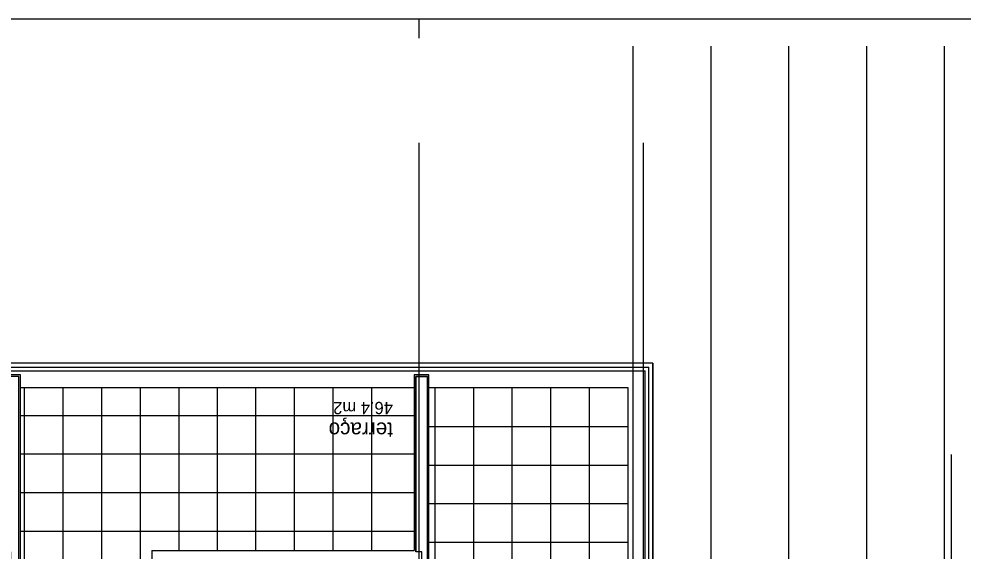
# Model space of a CAD drawing. Extents: x 1278 to 1356, y -253.7 to -224.
# Drawn here: x 1291.33 to 1303.56, y -230.86 to -223.96 of the extents above; entities that cross this region are included whole.
import ezdxf

# ---------------------------------------------------------------- set-up
doc = ezdxf.new("R2010")
doc.units = 0
for name, color, linetype in [('Level 1', 7, 'Continuous'), ('Level 2', 7, 'Continuous'), ('Level 21', 7, 'Continuous'), ('Level 60', 7, 'Continuous'), ('Level 62', 7, 'Continuous'), ('Level 65', 7, 'Continuous'), ('Level 67', 7, 'Continuous'), ('Level 68', 7, 'Continuous'), ('Level 70', 7, 'Continuous'), ('Level 93', 7, 'Continuous')]:
    doc.layers.add(name, color=color, linetype=linetype)

msp = doc.modelspace()

# ---------------------------------------------------------------- linework, layer by layer
at = {"layer": 'Level 1'}
for p, q in [((1291.334, -228.594), (1291.184, -228.594)), ((1291.334, -239.254), (1291.334, -228.594)), ((1296.473, -228.594), (1296.473, -230.87)), ((1296.623, -228.594), (1296.473, -228.594)), ((1296.623, -236.569), (1296.623, -228.594))]:
    msp.add_line(p, q, dxfattribs=at)
at = {"layer": 'Level 2'}
for p, q in [((1296.494, -228.424), (1291.194, -228.424)), ((1291.194, -228.474), (1296.494, -228.474)), ((1291.194, -228.524), (1296.494, -228.524)), ((1299.543, -228.424), (1296.493, -228.424)), ((1296.493, -228.474), (1299.493, -228.474)), ((1296.493, -228.524), (1299.443, -228.524)), ((1299.443, -231.924), (1299.443, -228.524)), ((1299.493, -231.924), (1299.493, -228.474)), ((1299.543, -231.924), (1299.543, -228.424)), ((1299.543, -228.424), (1299.543, -231.924)), ((1296.453, -228.744), (1291.354, -228.744)), ((1299.223, -228.744), (1296.643, -228.744)), ((1299.223, -231.924), (1299.223, -228.744))]:
    msp.add_line(p, q, dxfattribs=at)
at = {"layer": 'Level 21'}
for p, q in [((1291.404, -228.744), (1291.404, -232.77)), ((1291.904, -228.744), (1291.904, -232.77)), ((1292.404, -228.744), (1292.404, -239.104)), ((1292.904, -228.744), (1292.904, -239.104)), ((1293.404, -228.744), (1293.404, -230.85)), ((1293.904, -230.85), (1293.904, -228.744)), ((1294.404, -230.85), (1294.404, -228.744)), ((1294.904, -230.85), (1294.904, -228.744)), ((1295.404, -230.85), (1295.404, -228.744)), ((1295.904, -230.85), (1295.904, -228.744)), ((1296.723, -231.924), (1296.723, -228.744)), ((1297.223, -231.924), (1297.223, -228.744)), ((1297.723, -231.924), (1297.723, -228.744)), ((1298.223, -231.924), (1298.223, -228.744)), ((1298.723, -231.924), (1298.723, -228.744)), ((1296.453, -229.104), (1291.354, -229.104)), ((1296.643, -229.244), (1299.223, -229.244)), ((1296.453, -229.604), (1291.354, -229.604)), ((1296.643, -229.744), (1299.223, -229.744)), ((1296.453, -230.104), (1291.354, -230.104)), ((1296.643, -230.244), (1299.223, -230.244)), ((1296.453, -230.604), (1291.354, -230.604)), ((1296.643, -230.744), (1299.223, -230.744))]:
    msp.add_line(p, q, dxfattribs=at)
at = {"layer": 'Level 62'}
msp.add_lwpolyline([(1355.966, -223.959), (1355.966, -253.659), (1278.016, -253.659), (1278.016, -223.959)], close=True, dxfattribs=at)
at = {"layer": 'Level 65'}
for p, q in [((1291.354, -228.574), (1291.164, -228.574)), ((1291.354, -232.77), (1291.354, -228.574)), ((1296.453, -228.574), (1296.453, -230.85)), ((1296.643, -228.574), (1296.453, -228.574)), ((1296.643, -236.545), (1296.643, -228.574)), ((1293.054, -230.85), (1296.453, -230.85)), ((1293.054, -230.85), (1293.054, -231.18))]:
    msp.add_line(p, q, dxfattribs=at)
at = {"layer": 'Level 67'}
for points in [[(1291.184, -239.254), (1291.334, -239.254), (1291.334, -228.594), (1291.184, -228.594), (1291.184, -230.87), (1291.224, -230.87), (1291.224, -233.114), (1291.184, -233.114)], [(1296.473, -230.87), (1296.473, -228.594), (1296.623, -228.594), (1296.623, -236.569), (1297.724, -236.569), (1297.724, -236.639), (1296.553, -236.639), (1296.553, -230.87)]]:
    msp.add_lwpolyline(points, close=True, dxfattribs=at)
at = {"layer": 'Level 68'}
msp.add_line((1296.516, -224.209), (1296.516, -223.959), dxfattribs=at)
at = {"layer": 'Level 70'}
for p, q in [((1296.519, -250.792), (1296.519, -225.567)), ((1299.42, -250.792), (1299.42, -225.567)), ((1303.409, -250.792), (1303.409, -229.609))]:
    msp.add_line(p, q, dxfattribs=at)
at = {"layer": 'Level 93'}
for p, q in [((1299.289, -235.304), (1299.289, -224.312)), ((1300.297, -235.304), (1300.297, -224.312)), ((1301.304, -235.304), (1301.304, -224.312)), ((1302.312, -235.304), (1302.312, -224.312)), ((1303.319, -235.304), (1303.319, -224.312))]:
    msp.add_line(p, q, dxfattribs=at)

# ---------------------------------------------------------------- texts
at = {"layer": 'Level 60'}
for s, height, p in [('46.4 m2', 0.16, (1296.177, -228.925)), ('terraço', 0.2, (1296.177, -229.192))]:
    msp.add_text(s, height=height, rotation=180, dxfattribs=at).set_placement(p)

doc.saveas('drawing.dxf')
